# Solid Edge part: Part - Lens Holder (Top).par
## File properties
Author: hhakima
Template: Normal.par
Last saved by: Houman
Revision: 57
Application: Solid Edge
Material: Aluminum, 6061-T6
Face Style: Aluminum
Fill Style: ANSI38(Aluminum)
Virtual Style: Polished aluminum
Coef. of Thermal Exp: 2.3e-05
Thermal Conductivity: 180.0
Specific Heat: 920.0
Modulus of Elasticity: 68947570000.0
Poission's Ratio: 0.33
Yield Stress: 275790280.0
Ultimate Stress: 310264065.0
Elongation: 0.0
Density: 2712.000 kg/m^3
Accuracy: 0.990
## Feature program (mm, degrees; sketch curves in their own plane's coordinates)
sketch for "unnamed Protrusion 1" plane through (0, 0, 0) normal (0, 0, 1) x-axis (1, 0, 0)
  line (36.7117, 26.7297) -> (36.7117, 1.7297)
  line (36.7117, 1.7297) -> (61.7117, 1.7297)
  line (61.7117, 1.7297) -> (61.7117, 26.7297)
  line (61.7117, 26.7297) -> (36.7117, 26.7297)
extrude "unnamed Protrusion 1" add finite 5 along +normal
sketch for "ExtrudedCutout_1" plane through (49.2117, 14.2297, 5) normal (0, 0, 1) x-axis (1, 0, 0)
  circle centre (0, 0) radius 6.25
extrude "ExtrudedCutout_1" cut finite 4.5 along -normal
sketch for "ExtrudedCutout_2" plane through (49.2117, 14.2297, 0.5) normal (0, 0, 1) x-axis (0, 1, 0)
  circle centre (0, 0) radius 5
extrude "ExtrudedCutout_2" cut finite 2 along -normal
sketch for "ExtrudedCutout_17" #1 plane through (49.2117, 14.2297, 0) normal (0, 0, -1) x-axis (0, 1, 0)
  line (-12.5, 6.5) -> (-8.5, 6.5)
  line (-8.5, 6.5) -> (-8.5, -6.5)
  line (-8.5, -6.5) -> (-12.5, -6.5)
  line (-12.5, -6.5) -> (-12.5, 6.5)
  dimension (linear) = 12.5
  dimension (linear) = 8.5
  dimension (linear) = 6.5
  dimension (linear) = 6.5
sketch for "ExtrudedCutout_17" #2 plane through (49.2117, 14.2297, 0) normal (0, 0, -1) x-axis (0, 1, 0)
  line (12.5, 6.5) -> (12.5, -6.5)
  line (12.5, -6.5) -> (8.5, -6.5)
  line (8.5, -6.5) -> (8.5, 6.5)
  line (8.5, 6.5) -> (12.5, 6.5)
sketch for "ExtrudedCutout_17" #3 plane through (49.2117, 14.2297, 0) normal (0, 0, -1) x-axis (0, 1, 0)
  line (-6.5, 12.5) -> (-6.5, 8.5)
  line (-6.5, 8.5) -> (-2.5, 8.5)
  line (-2.5, 8.5) -> (-2.5, 12.5)
  line (-2.5, 12.5) -> (-6.5, 12.5)
sketch for "ExtrudedCutout_17" #4 plane through (49.2117, 14.2297, 0) normal (0, 0, -1) x-axis (0, 1, 0)
extrude "ExtrudedCutout_17" cut finite 6 along -normal
sketch for "unnamed Hole 1" plane through (49.2117, 14.2297, 0) normal (0, 0, -1) x-axis (0, 1, 0)
hole "unnamed Hole 1" through
sketch for "unnamed Hole 2" plane through (49.2117, 14.2297, 0) normal (0, 0, -1) x-axis (0, 1, 0)
  hole centre (-3.5, -10) bore radius 1.0065
hole "unnamed Hole 2" through
sketch for "unnamed Hole 3" plane through (49.2117, 14.2297, 0) normal (0, 0, -1) x-axis (0, 1, 0)
hole "unnamed Hole 3" through
pattern "unnamed Pattern 1" of "unnamed Hole 1", "unnamed Hole 2", "unnamed Hole 3"
sketch for "unnamed Hole 4" plane through (49.2117, 14.2297, 0) normal (0, 0, -1) x-axis (0, 1, 0)
hole "unnamed Hole 4" finite
mirror "unnamed Mirror 1" of "unnamed Hole 4" about plane through (61.7117, 26.7297, 5) normal (-0.707107, 0.707107, 0)
hole "unnamed Hole 5" finite
mirror "unnamed Mirror 2" of "unnamed Mirror 1" about plane through (49.2117, 14.2297, 2.5) normal (1, 0, 0)
hole "unnamed Hole 6" finite
sketch for "ExtrudedCutout_18" plane through (49.2117, 14.2297, 0) normal (0, 0, -1) x-axis (0, 1, 0)
extrude "ExtrudedCutout_18" cut finite 1 along -normal
mirror "unnamed Mirror 3" of "ExtrudedCutout_18" about plane through (61.7117, 26.7297, 5) normal (-0.707107, 0.707107, 0)
extrude "unnamed Cutout 1" cut finite 1
mirror "unnamed Mirror 4" of "unnamed Mirror 3" about plane through (49.2117, 14.2297, 2.5) normal (1, 0, 0)
extrude "unnamed Cutout 2" cut finite 1
mirror "unnamed Mirror 5" of "unnamed Mirror 4" about plane through (61.7117, 1.7297, 0) normal (-0.707107, -0.707107, 0)
extrude "unnamed Cutout 3" cut finite 1
sketch for "unnamed Cutout 4" #1 plane through (49.2117, 14.2297, 5) normal (0, 0, 1) x-axis (0, -1, 0)
sketch for "unnamed Cutout 4" #2 plane through (49.2117, 14.2297, 5) normal (0, 0, 1) x-axis (0, -1, 0)
extrude "unnamed Cutout 4" cut finite 3 along -normal
mirror "unnamed Mirror 6" of "unnamed Mirror 2" about plane through (61.7117, 1.7297, 0) normal (-0.707107, -0.707107, 0)
hole "unnamed Hole 7" finite
sketch for "Hole_20" plane through (58.7117, 4.7297, 1) normal (0, 0, -1) x-axis (0, 1, 0)
hole "Hole_20" diameter 3 through
mirror "unnamed Mirror 7" of "Hole_20" about plane through (61.7117, 26.7297, 5) normal (-0.707107, 0.707107, 0)
hole "unnamed Hole 8" through
mirror "unnamed Mirror 8" of "Hole_20" about plane through (49.2117, 14.2297, 2.5) normal (1, 0, 0)
hole "unnamed Hole 9" through
mirror "unnamed Mirror 9" of "unnamed Mirror 7"
pattern "unnamed Pattern 2"
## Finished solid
Body 1: solid body, 54 faces, 121 edges, 62 vertices.
  Faces by surface: plane 39, cylinder 15
  Edges by curve: line 88, circle 33
Bounding box of the edges (mm): 25.000 x 25.000 x 5.000, from (36.7117, 1.7297, 0) to (61.7117, 26.7297, 5).
Cylindrical faces by radius (mm): R1.0065 x3, R1.5 x4, R1.5875 x4, R2.5 x2, R5 x1, R6.25 x1
Planar faces by outward normal: +x 7, +y 6, +z 4, -x 3, -y 6, -z 9, oblique 4
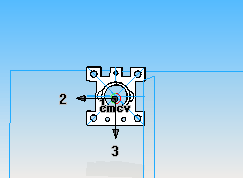
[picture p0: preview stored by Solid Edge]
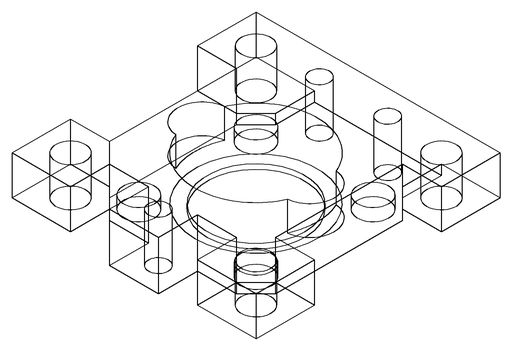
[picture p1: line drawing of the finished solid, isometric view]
